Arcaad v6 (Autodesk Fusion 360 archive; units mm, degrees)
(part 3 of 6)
sketch "Sketch4" plane through (0, 7.7192, 43.7775) normal (0, 0.1736, 0.9848) x axis (1, 0, 0)
  line L1 (-288, 337.4354) -> (-288, 349.4354)
  line L2 (288, 337.4354) -> (-288, 337.4354)
  line L3 (288, 349.4354) -> (288, 337.4354)
  line L4 (-288, 349.4354) -> (288, 349.4354)
  line L5 (288, 349.4354) -> (-288, 349.4354)
  line L6 (288, 337.4354) -> (288, 349.4354)
  line L7 (-288, 337.4354) -> (288, 337.4354)
  line L8 (-288, 349.4354) -> (-288, 337.4354)
  line L9 (288, 343.4354) -> (-288, 343.4354)
  line L10 (110, -245.5646) -> (110, 244.4354)
  line L11 (-110, -245.5646) -> (110, -245.5646)
  line L12 (-110, 244.4354) -> (-110, -245.5646)
  line L13 (110, 244.4354) -> (-110, 244.4354)
  line L14 (288, 249.4354) -> (288, 149.4354)
  line L15 (294, 249.4354) -> (288, 249.4354)
  line L16 (294, 224.4354) -> (294, 249.4354)
  line L17 (300, 224.4354) -> (294, 224.4354)
  line L18 (300, 349.4354) -> (300, 224.4354)
  line L19 (150, 349.4354) -> (300, 349.4354)
  line L20 (150, 343.4354) -> (150, 349.4354)
  line L21 (175, 343.4354) -> (150, 343.4354)
  line L22 (175, 337.4354) -> (175, 343.4354)
  line L23 (75, 337.4354) -> (175, 337.4354)
  line L24 (75, 343.4354) -> (75, 337.4354)
  line L25 (100, 343.4354) -> (75, 343.4354)
  line L26 (100, 349.4354) -> (100, 343.4354)
  line L27 (-75, 349.4354) -> (100, 349.4354)
  line L28 (-75, 343.4354) -> (-75, 349.4354)
  line L29 (-50, 343.4354) -> (-75, 343.4354)
  line L30 (-50, 337.4354) -> (-50, 343.4354)
  line L31 (-175, 337.4354) -> (-50, 337.4354)
  line L32 (-175, 343.4354) -> (-175, 337.4354)
  line L33 (-150, 343.4354) -> (-175, 343.4354)
  line L34 (-150, 349.4354) -> (-150, 343.4354)
  line L35 (-300, 349.4354) -> (-150, 349.4354)
  line L36 (-300, 224.4354) -> (-300, 349.4354)
  line L37 (-294, 224.4354) -> (-300, 224.4354)
  line L38 (-294, 249.4354) -> (-294, 224.4354)
  line L39 (-288, 249.4354) -> (-294, 249.4354)
  line L40 (-288, 149.4354) -> (-288, 249.4354)
  line L41 (-294, 149.4354) -> (-288, 149.4354)
  line L42 (-294, 174.4354) -> (-294, 149.4354)
  line L43 (-300, 174.4354) -> (-294, 174.4354)
  line L44 (-300, 24.4354) -> (-300, 174.4354)
  line L45 (-294, 24.4354) -> (-300, 24.4354)
  line L46 (-294, 49.4354) -> (-294, 24.4354)
  line L47 (-288, 49.4354) -> (-294, 49.4354)
  line L48 (-288, -50.5646) -> (-288, 49.4354)
  line L49 (-294, -50.5646) -> (-288, -50.5646)
  line L50 (-294, -25.5646) -> (-294, -50.5646)
  line L51 (-300, -25.5646) -> (-294, -25.5646)
  line L52 (-300, -175.5646) -> (-300, -25.5646)
  line L53 (-294, -175.5646) -> (-300, -175.5646)
  line L54 (-294, -150.5646) -> (-294, -175.5646)
  line L55 (-288, -150.5646) -> (-294, -150.5646)
  line L56 (-288, -250.5646) -> (-288, -150.5646)
  line L57 (-294, -250.5646) -> (-288, -250.5646)
  line L58 (-294, -225.5646) -> (-294, -250.5646)
  line L59 (-300, -225.5646) -> (-294, -225.5646)
  line L60 (-300, -350.5646) -> (-300, -225.5646)
  line L61 (-150, -350.5646) -> (-300, -350.5646)
  line L62 (-150, -344.5646) -> (-150, -350.5646)
  line L63 (-175, -344.5646) -> (-150, -344.5646)
  line L64 (-175, -338.5646) -> (-175, -344.5646)
  line L65 (-75, -338.5646) -> (-175, -338.5646)
  line L66 (-75, -344.5646) -> (-75, -338.5646)
  line L67 (-100, -344.5646) -> (-75, -344.5646)
  line L68 (-100, -350.5646) -> (-100, -344.5646)
  line L69 (100, -350.5646) -> (-100, -350.5646)
  line L70 (100, -344.5646) -> (100, -350.5646)
  line L71 (75, -344.5646) -> (100, -344.5646)
  line L72 (75, -338.5646) -> (75, -344.5646)
  line L73 (175, -338.5646) -> (75, -338.5646)
  line L74 (175, -344.5646) -> (175, -338.5646)
  line L75 (150, -344.5646) -> (175, -344.5646)
  line L76 (150, -350.5646) -> (150, -344.5646)
  line L77 (300, -350.5646) -> (150, -350.5646)
  line L78 (300, -225.5646) -> (300, -350.5646)
  line L79 (294, -225.5646) -> (300, -225.5646)
  line L80 (294, -250.5646) -> (294, -225.5646)
  line L81 (288, -250.5646) -> (294, -250.5646)
  line L82 (288, -150.5646) -> (288, -250.5646)
  line L83 (294, -150.5646) -> (288, -150.5646)
  line L84 (294, -175.5646) -> (294, -150.5646)
  line L85 (300, -175.5646) -> (294, -175.5646)
  line L86 (300, -25.5646) -> (300, -175.5646)
  line L87 (294, -25.5646) -> (300, -25.5646)
  line L88 (294, -50.5646) -> (294, -25.5646)
  line L89 (288, -50.5646) -> (294, -50.5646)
  line L90 (288, 49.4354) -> (288, -50.5646)
  line L91 (294, 49.4354) -> (288, 49.4354)
  line L92 (294, 24.4354) -> (294, 49.4354)
  line L93 (300, 24.4354) -> (294, 24.4354)
  line L94 (300, 174.4354) -> (300, 24.4354)
  line L95 (294, 174.4354) -> (300, 174.4354)
  line L96 (294, 149.4354) -> (294, 174.4354)
  line L97 (288, 149.4354) -> (294, 149.4354)
  line L98 (-175, 349.4354) -> (-175, 343.4354)
  line L99 (-50, 349.4354) -> (-50, 343.4354)
  line L100 (175, 349.4354) -> (175, 343.4354)
  line L101 (75, 349.4354) -> (75, 343.4354)
  line L102 (100, 337.4354) -> (100, 343.4354)
  line L103 (150, 337.4354) -> (150, 343.4354)
  line L104 (-75, 337.4354) -> (-75, 343.4354)
  line L105 (-150, 337.4354) -> (-150, 343.4354)
  point P4 (288, 337.4354)
  point P8 (288, 337.4354)
  point P2 (-288, 349.4354)
  point P6 (-288, 349.4354)
  point P35 (-175, 343.4354)
  point P100 (-175, 343.4354)
  point P101 (-175, 349.4354)
  point P32 (-50, 343.4354)
  point P102 (-50, 343.4354)
  point P24 (175, 343.4354)
  point P104 (175, 343.4354)
  point P27 (75, 343.4354)
  point P106 (75, 343.4354)
  point P28 (100, 343.4354)
  point P108 (100, 343.4354)
  point P23 (150, 343.4354)
  point P110 (150, 343.4354)
  point P31 (-75, 343.4354)
  point P112 (-75, 343.4354)
  point P36 (-150, 343.4354)
  point P114 (-150, 343.4354)
  point P103 (-50, 349.4354)
  point P105 (175, 349.4354)
  point P107 (75, 349.4354)
  point P109 (100, 337.4354)
  point P111 (150, 337.4354)
  point P113 (-75, 337.4354)
  point P115 (-150, 337.4354)
  horizontal L5
  vertical L6
  horizontal L7
  vertical L8
  coincident P4 P8
  coincident P2 P6
  coincident P35 P100
  coincident L5 P101
  coincident P32 P102
  perpendicular L5 L99
  coincident P24 P104
  perpendicular L5 L100
  coincident P27 P106
  perpendicular L27 L101
  coincident P28 P108
  perpendicular L7 L102
  coincident P23 P110
  perpendicular L23 L103
  coincident P31 P112
  perpendicular L7 L104
  coincident P36 P114
  perpendicular L31 L105
  dimension "d37" = 6
  dimension "d201" distance P100 P101 = 6
  dimension "d202" distance P102 P103 = 6
  dimension "d203" distance P104 P105 = 6
  dimension "d204" distance P106 P107 = 6
  dimension "d205" distance P108 P109 = 6
  dimension "d206" distance P110 P111 = 6
  dimension "d207" distance P112 P113 = 6
  dimension "d208" distance P114 P115 = 6
extrude "Extrude5" add sketch "Sketch4" profile of L2 L4 L5 L7 L9 L19 L20 L21 L23 L25 L26 L27 L28 L29 L31 L33 L34 L35 L98 L99 L100 L101 L102 L103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 along normal blind 12
sketch "Sketch5" plane through (0, 7.7192, 43.7775) normal (0, 0.1736, 0.9848) x axis (1, 0, 0)
  line L1 (175, 349.4354) -> (288, 349.4354)
  line L2 (288, 337.4354) -> (150, 337.4354)
  line L3 (110, -245.5646) -> (110, 244.4354)
  line L4 (-110, -245.5646) -> (110, -245.5646)
  line L5 (-110, 244.4354) -> (-110, -245.5646)
  line L6 (110, 244.4354) -> (-110, 244.4354)
  line L7 (288, 249.4354) -> (288, 149.4354)
  line L8 (294, 249.4354) -> (288, 249.4354)
  line L9 (294, 224.4354) -> (294, 249.4354)
  line L10 (300, 224.4354) -> (294, 224.4354)
  line L11 (300, 349.4354) -> (300, 224.4354)
  line L12 (150, 349.4354) -> (300, 349.4354)
  line L13 (150, 343.4354) -> (150, 349.4354)
  line L14 (175, 343.4354) -> (150, 343.4354)
  line L15 (175, 337.4354) -> (175, 343.4354)
  line L16 (75, 337.4354) -> (175, 337.4354)
  line L17 (75, 343.4354) -> (75, 337.4354)
  line L18 (100, 343.4354) -> (75, 343.4354)
  line L19 (100, 349.4354) -> (100, 343.4354)
  line L20 (-75, 349.4354) -> (100, 349.4354)
  line L21 (-75, 343.4354) -> (-75, 349.4354)
  line L22 (-50, 343.4354) -> (-75, 343.4354)
  line L23 (-50, 337.4354) -> (-50, 343.4354)
  line L24 (-175, 337.4354) -> (-50, 337.4354)
  line L25 (-175, 343.4354) -> (-175, 337.4354)
  line L26 (-150, 343.4354) -> (-175, 343.4354)
  line L27 (-150, 349.4354) -> (-150, 343.4354)
  line L28 (-300, 349.4354) -> (-150, 349.4354)
  line L29 (-300, 224.4354) -> (-300, 349.4354)
  line L30 (-294, 224.4354) -> (-300, 224.4354)
  line L31 (-294, 249.4354) -> (-294, 224.4354)
  line L32 (-288, 249.4354) -> (-294, 249.4354)
  line L33 (-288, 149.4354) -> (-288, 249.4354)
  line L34 (-294, 149.4354) -> (-288, 149.4354)
  line L35 (-294, 174.4354) -> (-294, 149.4354)
  line L36 (-300, 174.4354) -> (-294, 174.4354)
  line L37 (-300, 24.4354) -> (-300, 174.4354)
  line L38 (-294, 24.4354) -> (-300, 24.4354)
  line L39 (-294, 49.4354) -> (-294, 24.4354)
  line L40 (-288, 49.4354) -> (-294, 49.4354)
  line L41 (-288, -50.5646) -> (-288, 49.4354)
  line L42 (-294, -50.5646) -> (-288, -50.5646)
  line L43 (-294, -25.5646) -> (-294, -50.5646)
  line L44 (-300, -25.5646) -> (-294, -25.5646)
  line L45 (-300, -175.5646) -> (-300, -25.5646)
  line L46 (-294, -175.5646) -> (-300, -175.5646)
  line L47 (-294, -150.5646) -> (-294, -175.5646)
  line L48 (-288, -150.5646) -> (-294, -150.5646)
  line L49 (-288, -250.5646) -> (-288, -150.5646)
  line L50 (-294, -250.5646) -> (-288, -250.5646)
  line L51 (-294, -225.5646) -> (-294, -250.5646)
  line L52 (-300, -225.5646) -> (-294, -225.5646)
  line L53 (-300, -350.5646) -> (-300, -225.5646)
  line L54 (-150, -350.5646) -> (-300, -350.5646)
  line L55 (-150, -344.5646) -> (-150, -350.5646)
  line L56 (-175, -344.5646) -> (-150, -344.5646)
  line L57 (-175, -338.5646) -> (-175, -344.5646)
  line L58 (-75, -338.5646) -> (-175, -338.5646)
  line L59 (-75, -344.5646) -> (-75, -338.5646)
  line L60 (-100, -344.5646) -> (-75, -344.5646)
  line L61 (-100, -350.5646) -> (-100, -344.5646)
  line L62 (100, -350.5646) -> (-100, -350.5646)
  line L63 (100, -344.5646) -> (100, -350.5646)
  line L64 (75, -344.5646) -> (100, -344.5646)
  line L65 (75, -338.5646) -> (75, -344.5646)
  line L66 (175, -338.5646) -> (75, -338.5646)
  line L67 (175, -344.5646) -> (175, -338.5646)
  line L68 (150, -344.5646) -> (175, -344.5646)
  line L69 (150, -350.5646) -> (150, -344.5646)
  line L70 (300, -350.5646) -> (150, -350.5646)
  line L71 (300, -225.5646) -> (300, -350.5646)
  line L72 (294, -225.5646) -> (300, -225.5646)
  line L73 (294, -250.5646) -> (294, -225.5646)
  line L74 (288, -250.5646) -> (294, -250.5646)
  line L75 (288, -150.5646) -> (288, -250.5646)
  line L76 (294, -150.5646) -> (288, -150.5646)
  line L77 (294, -175.5646) -> (294, -150.5646)
  line L78 (300, -175.5646) -> (294, -175.5646)
  line L79 (300, -25.5646) -> (300, -175.5646)
  line L80 (294, -25.5646) -> (300, -25.5646)
  line L81 (294, -50.5646) -> (294, -25.5646)
  line L82 (288, -50.5646) -> (294, -50.5646)
  line L83 (288, 49.4354) -> (288, -50.5646)
  line L84 (294, 49.4354) -> (288, 49.4354)
  line L85 (294, 24.4354) -> (294, 49.4354)
  line L86 (300, 24.4354) -> (294, 24.4354)
  line L87 (300, 174.4354) -> (300, 24.4354)
  line L88 (294, 174.4354) -> (300, 174.4354)
  line L89 (294, 149.4354) -> (294, 174.4354)
  line L90 (288, 149.4354) -> (294, 149.4354)
  line L91 (288, 337.4354) -> (-288, 337.4354)
  line L92 (288, 387.4354) -> (288, 337.4354)
  line L93 (-288, 387.4354) -> (288, 387.4354)
  line L94 (-288, 337.4354) -> (-288, 387.4354)
  line L95 (288, 349.4354) -> (-288, 349.4354)
  line L96 (288, 337.4354) -> (288, 349.4354)
  line L97 (-288, 337.4354) -> (288, 337.4354)
  line L98 (-288, 349.4354) -> (-288, 337.4354)
  line L99 (-288, 349.4354) -> (288, 349.4354)
  line L100 (-288, 337.4354) -> (-288, 349.4354)
  line L101 (288, 337.4354) -> (-288, 337.4354)
  line L102 (288, 349.4354) -> (288, 337.4354)
  line L103 (150, 337.4354) -> (150, 343.4354)
  line L104 (288, 349.4354) -> (288, 337.4354)
  line L105 (175, 343.4354) -> (175, 349.4354)
  line L106 (150, 343.4354) -> (175, 343.4354)
  line L107 (-150, 343.4354) -> (-150, 337.4354)
  line L108 (-175, 343.4354) -> (-150, 343.4354)
  line L109 (-175, 349.4354) -> (-175, 343.4354)
  line L110 (-288, 349.4354) -> (-175, 349.4354)
  line L111 (-288, 337.4354) -> (-288, 349.4354)
  line L112 (-150, 337.4354) -> (-288, 337.4354)
  line L113 (-50, 349.4354) -> (-50, 337.4354)
  line L114 (-75, 337.4354) -> (-75, 343.4354)
  line L115 (150, 337.4354) -> (150, 343.4354)
  line L116 (100, 337.4354) -> (100, 343.4354)
  line L117 (75, 349.4354) -> (75, 343.4354)
  line L118 (175, 349.4354) -> (175, 343.4354)
  line L119 (-150, 349.4354) -> (-150, 343.4354)
  line L120 (-75, 349.4354) -> (-75, 343.4354)
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  point P94 (-288, 337.4354)
  point P98 (-288, 337.4354)
  point P99 (-288, 349.4354)
  point P102 (-288, 349.4354)
  point P104 (-288, 337.4354)
  point P27 (-50, 337.4354)
  point P115 (-50, 337.4354)
  point P114 (-50, 349.4354)
  point P116 (-50, 349.4354)
  point P25 (-75, 343.4354)
  point P118 (-75, 343.4354)
  point P117 (-75, 337.4354)
  point P119 (-75, 337.4354)
  point P106 (150, 343.4354)
  point P120 (150, 343.4354)
  point P5 (150, 337.4354)
  point P121 (150, 337.4354)
  point P22 (100, 343.4354)
  point P123 (100, 343.4354)
  point P122 (100, 337.4354)
  point P124 (100, 337.4354)
  point P21 (75, 343.4354)
  point P126 (75, 343.4354)
  point P125 (75, 349.4354)
  point P127 (75, 349.4354)
  point P107 (175, 343.4354)
  point P128 (175, 343.4354)
  point P4 (175, 349.4354)
  point P129 (175, 349.4354)
  point P109 (-150, 343.4354)
  point P130 (-150, 343.4354)
  point P31 (-150, 349.4354)
  point P131 (-150, 349.4354)
  point P132 (-75, 343.4354)
  point P24 (-75, 349.4354)
  point P133 (-75, 349.4354)
  point P134 (100, 343.4354)
  point P23 (100, 349.4354)
  point P135 (100, 349.4354)
  point P17 (150, 343.4354)
  point P136 (150, 343.4354)
  point P16 (150, 349.4354)
  point P137 (150, 349.4354)
  point P97 (-288, 387.4354)
  horizontal L91
  vertical L92
  horizontal L93
  vertical L94
  coincident P94 P98
  horizontal L95
  vertical L96
  horizontal L97
  vertical L98
  coincident P99 P102
  horizontal L99
  vertical L100
  horizontal L101
  vertical L102
  coincident P98 P104
  coincident P27 P115
  coincident P114 P116
  coincident P25 P118
  coincident P117 P119
  coincident P106 P120
  coincident P5 P121
  coincident P22 P123
  coincident P122 P124
  coincident P21 P126
  coincident P125 P127
  coincident P107 P128
  coincident P4 P129
  coincident P109 P130
  coincident P31 P131
  coincident P25 P132
  coincident P24 P133
  coincident P22 P134
  coincident P23 P135
  coincident P17 P136
  coincident P16 P137
  dimension "d40" distance P94 P97 = 50
extrude "Extrude6" new body sketch "Sketch5" to an object
sketch "Sketch6" plane through (-288, 0, 0) normal (-1, 0, 0) x axis (0, 0, 1)
  line L1 (-64.0579, 331.3458) -> (-66.1417, 343.1635)
  line L2 (-14.8175, 340.0282) -> (-64.0579, 331.3458)
  line L3 (-16.9013, 351.8459) -> (-14.8175, 340.0282)
  line L4 (-66.1417, 343.1635) -> (-16.9013, 351.8459)
  line L5 (-11.6822, 391.3524) -> (-2.9998, 342.112)
  line L6 (-23.4999, 389.2686) -> (-11.6822, 391.3524)
  line L7 (-14.8175, 340.0282) -> (-23.4999, 389.2686)
  line L8 (-66.1417, 343.1635) -> (55.412, -346.2019)
  line L9 (-312.3436, 299.7514) -> (-66.1417, 343.1635)
  line L10 (-190.7899, -389.614) -> (-312.3436, 299.7514)
  line L11 (55.412, -346.2019) -> (-190.7899, -389.614)
  line L12 (-344.588, -346.2019) -> (55.412, -346.2019)
  line L13 (-312.3436, -346.2019) -> (-312.3436, 299.7514)
  line L14 (-312.3436, 426.9121) -> (-312.3436, -346.2019)
  line L15 (-312.3436, 389.2686) -> (-23.4999, 389.2686)
  line L16 (-64.0579, 331.3458) -> (-14.8175, 340.0282)
  line L17 (-2.9998, 342.112) -> (-14.8175, 340.0282)
  point P10 (55.412, -346.2019)
  point P14 (55.412, -346.2019)
  point P12 (-312.3436, 299.7514)
  point P16 (-312.3436, 299.7514)
  point P17 (-312.3436, -346.2019)
  point P8 (-23.4999, 389.2686)
  point P19 (-23.4999, 389.2686)
  point P20 (-312.3436, 389.2686)
  point P9 (-14.8175, 340.0282)
  point P21 (-14.8175, 340.0282)
  point P3 (-64.0579, 331.3458)
  point P22 (-64.0579, 331.3458)
  point P15 (-344.588, -346.2019)
  coincident P10 P14
  coincident P12 P16
  coincident L12 P17
  perpendicular L12 L13
  parallel L13 L14
  coincident P8 P19
  coincident L14 P20
  perpendicular L14 L15
  coincident P9 P21
  coincident P3 P22
  dimension "d43" distance P14 P15 = 400
  dimension "d44" angle L8 L12 = 80
extrude "Extrude7" add sketch "Sketch6" profile of L1 L2 L3 L4 L5 L6 L7 L8 L9 L10 L12 L13 L14 L15 L16 to an object
sketch "Sketch7" plane through (288, 0, 0) normal (1, 0, 0) x axis (0, 0, -1)
  line L1 (66.1417, 343.1635) -> (64.0579, 331.3458)
  line L2 (16.9013, 351.8459) -> (66.1417, 343.1635)
  line L3 (14.8175, 340.0282) -> (16.9013, 351.8459)
  line L4 (64.0579, 331.3458) -> (14.8175, 340.0282)
  line L5 (-55.412, -346.2019) -> (64.0579, 331.3458)
  line L6 (190.7899, -389.614) -> (-55.412, -346.2019)
  line L7 (198.4446, -346.2019) -> (190.7899, -389.614)
  line L8 (312.3436, -346.2019) -> (198.4446, -346.2019)
  line L9 (312.3436, 389.2686) -> (312.3436, -346.2019)
  line L10 (23.4999, 389.2686) -> (312.3436, 389.2686)
  line L11 (11.6822, 391.3524) -> (23.4999, 389.2686)
  line L12 (2.9998, 342.112) -> (11.6822, 391.3524)
  line L13 (64.0579, 331.3458) -> (2.9998, 342.112)
extrude "Extrude8" add sketch "Sketch7" along normal blind 12
combine "Combine1"
combine "Combine2"
sketch "Sketch8" plane through (300, 0, 0) normal (1, 0, 0) x axis (0, 0, -1)
  line L1 (-21.8883, -225.1847) -> (-43.5944, -348.2857)
  line L2 (-33.706, -223.101) -> (-21.8883, -225.1847)
  line L3 (-55.412, -346.2019) -> (-33.706, -223.101)
  line L4 (-43.5944, -348.2857) -> (-55.412, -346.2019)
  line L5 (-287.6564, -346.2019) -> (312.3436, -346.2019)
  line L6 (-287.6564, -596.2019) -> (-287.6564, -346.2019)
  line L7 (312.3436, -596.2019) -> (-287.6564, -596.2019)
  line L8 (312.3436, -346.2019) -> (312.3436, -596.2019)
  line L9 (312.3436, -471.2019) -> (-287.6564, -471.2019)
  line L10 (-287.6564, -408.7019) -> (312.3436, -408.7019)
  line L11 (-287.6564, -408.7019) -> (-55.412, -346.2019)
  point P6 (312.3436, -346.2019)
  point P10 (312.3436, -346.2019)
  point P5 (-55.412, -346.2019)
  point P15 (-55.412, -346.2019)
  point P9 (312.3436, -596.2019)
  point P7 (-287.6564, -346.2019)
  horizontal L5
  vertical L6
  horizontal L7
  vertical L8
  coincident P6 P10
  coincident P5 P15
  dimension "d49" distance P6 P9 = 250
  dimension "d50" distance P6 P7 = 600
  dimension "d51" = -125 (= "-( ( 250 / 2 ) * 1 mm )")
  dimension "d52" = -62.5 (= "-( ( 250 / 4 ) * 1 mm )")
extrude "Extrude9" add sketch "Sketch8" profile of L1 L4 L5 L6 L7 L8 L9 L10 L11 against normal blind 12
sketch "Sketch9" plane through (-300, 0, 0) normal (-1, 0, 0) x axis (0, 0, 1)
  line L1 (13.2059, -175.9444) -> (25.0236, -173.8606)
  line L2 (-12.8413, -28.2232) -> (13.2059, -175.9444)
  line L3 (-1.0236, -26.1394) -> (-12.8413, -28.2232)
  line L4 (-9.706, 23.101) -> (-1.0236, -26.1394)
  line L5 (-21.5237, 21.0172) -> (-9.706, 23.101)
  line L6 (-47.5709, 168.7384) -> (-21.5237, 21.0172)
  line L7 (-35.7532, 170.8221) -> (-47.5709, 168.7384)
  line L8 (-44.4357, 220.0625) -> (-35.7532, 170.8221)
  line L9 (-56.2534, 217.9787) -> (-44.4357, 220.0625)
  line L10 (-77.9594, 341.0797) -> (-56.2534, 217.9787)
  line L11 (-66.1417, 343.1635) -> (-77.9594, 341.0797)
  line L12 (-64.0579, 331.3458) -> (-66.1417, 343.1635)
  line L13 (-2.9998, 342.112) -> (-64.0579, 331.3458)
  line L14 (-11.6822, 391.3524) -> (-2.9998, 342.112)
  line L15 (-23.4999, 389.2686) -> (-11.6822, 391.3524)
  line L16 (-312.3436, 389.2686) -> (-23.4999, 389.2686)
  line L17 (-312.3436, -346.2019) -> (-312.3436, 389.2686)
  line L18 (-198.4446, -346.2019) -> (-312.3436, -346.2019)
  line L19 (-190.7899, -389.614) -> (-198.4446, -346.2019)
  line L20 (43.5944, -348.2857) -> (-190.7899, -389.614)
  line L21 (21.8883, -225.1847) -> (43.5944, -348.2857)
  line L22 (33.706, -223.101) -> (21.8883, -225.1847)
  line L23 (25.0236, -173.8606) -> (33.706, -223.101)
  line L24 (26.2295, -249.8049) -> (43.5944, -348.2857)
  line L25 (38.0472, -247.7212) -> (26.2295, -249.8049)
  line L26 (20.6824, -149.2404) -> (38.0472, -247.7212)
  line L27 (8.8647, -151.3242) -> (20.6824, -149.2404)
  line L28 (-8.5001, -52.8434) -> (8.8647, -151.3242)
  line L29 (3.3176, -50.7596) -> (-8.5001, -52.8434)
  line L30 (-14.0472, 47.7212) -> (3.3176, -50.7596)
  line L31 (-25.8649, 45.6374) -> (-14.0472, 47.7212)
  line L32 (-43.2297, 144.1182) -> (-25.8649, 45.6374)
  line L33 (-31.412, 146.2019) -> (-43.2297, 144.1182)
  line L34 (-48.7769, 244.6827) -> (-31.412, 146.2019)
  line L35 (-60.5946, 242.5989) -> (-48.7769, 244.6827)
  line L36 (-77.9594, 341.0797) -> (-60.5946, 242.5989)
  line L37 (-66.1417, 343.1635) -> (-77.9594, 341.0797)
  line L38 (-64.0579, 331.3458) -> (-66.1417, 343.1635)
  line L39 (-2.9998, 342.112) -> (-64.0579, 331.3458)
  line L40 (-11.6822, 391.3524) -> (-2.9998, 342.112)
  line L41 (-23.4999, 389.2686) -> (-11.6822, 391.3524)
  line L42 (-312.3436, 389.2686) -> (-23.4999, 389.2686)
  line L43 (-312.3436, -596.2019) -> (-312.3436, 389.2686)
  line L44 (287.6564, -596.2019) -> (-312.3436, -596.2019)
  line L45 (287.6564, -408.7019) -> (287.6564, -596.2019)
  line L46 (55.412, -346.2019) -> (287.6564, -408.7019)
  line L47 (43.5944, -348.2857) -> (55.412, -346.2019)
  line L48 (43.5944, -348.2857) -> (21.8883, -225.1847)
  line L49 (55.412, -346.2019) -> (43.5944, -348.2857)
  line L50 (33.706, -223.101) -> (55.412, -346.2019)
  line L51 (21.8883, -225.1847) -> (33.706, -223.101)
  line L52 (13.2059, -175.9444) -> (-12.8413, -28.2232)
  line L53 (25.0236, -173.8606) -> (13.2059, -175.9444)
  line L54 (-1.0236, -26.1394) -> (25.0236, -173.8606)
  line L55 (-12.8413, -28.2232) -> (-1.0236, -26.1394)
  line L56 (-21.5237, 21.0172) -> (-47.5709, 168.7384)
  line L57 (-9.706, 23.101) -> (-21.5237, 21.0172)
  line L58 (-35.7532, 170.8221) -> (-9.706, 23.101)
  line L59 (-47.5709, 168.7384) -> (-35.7532, 170.8221)
  line L60 (-56.2534, 217.9787) -> (-77.9594, 341.0797)
  line L61 (-44.4357, 220.0625) -> (-56.2534, 217.9787)
  line L62 (-66.1417, 343.1635) -> (-44.4357, 220.0625)
  line L63 (-77.9594, 341.0797) -> (-66.1417, 343.1635)
extrude "Extrude10" add sketch "Sketch9" profile of L18 L19 L20 L43 L44 L45 L46 L47 L49 against normal blind 12
extrude "Extrude11" add of existing geometry to an object
sketch "Sketch10" plane through (0, 0, 287.6564) normal (0, 0, 1) x axis (1, 0, 0)
  line L1 (-300, -596.2019) -> (-300, -408.7019)
  line L2 (-288, -596.2019) -> (-300, -596.2019)
  line L3 (-288, -408.7019) -> (-288, -596.2019)
  line L4 (-300, -408.7019) -> (-288, -408.7019)
  line L5 (300, -408.7019) -> (-300, -408.7019)
  line L6 (300, -596.2019) -> (300, -408.7019)
  line L7 (-300, -596.2019) -> (300, -596.2019)
  line L8 (-300, -408.7019) -> (-300, -596.2019)
  line L9 (300, -408.7019) -> (300, -596.2019)
  line L10 (288, -408.7019) -> (300, -408.7019)
  line L11 (288, -596.2019) -> (288, -408.7019)
  line L12 (300, -596.2019) -> (288, -596.2019)
  line L13 (300, -502.4519) -> (-300, -502.4519)
  line L14 (300, -552.4519) -> (-300, -552.4519)
  line L15 (300, -527.4519) -> (-300, -527.4519)
  line L16 (300, -477.4519) -> (-300, -477.4519)
  line L17 (300, -452.4519) -> (-300, -452.4519)
  line L18 (-294, -408.7019) -> (-294, -596.2019)
  line L19 (294, -596.2019) -> (294, -408.7019)
  point P8 (300, -596.2019)
  point P10 (300, -596.2019)
  point P2 (-300, -408.7019)
  point P6 (-300, -408.7019)
  point P15 (-300, -502.4519)
  point P16 (300, -502.4519)
  horizontal L5
  vertical L6
  horizontal L7
  vertical L8
  coincident P8 P10
  coincident P2 P6
  midpoint L8 P15
  midpoint L9 P16
  dimension "d59" = 50
  dimension "d60" = 25 (= "( 50 / 2 ) * 1 mm")
  dimension "d61" = -25 (= "-( ( 50 / 2 ) * 1 mm )")
  dimension "d62" = -50
  dimension "d63" = 6
  dimension "d64" = 6
extrude "Extrude12" add sketch "Sketch10" profile of L1 L3 L6 L8 L9 L11 L13 L14 L15 L16 L17 L18 L19 along normal blind 12
extrude "Extrude13" new body sketch "Sketch10" along normal blind 12
sketch "Sketch11" plane through (-300, 0, 0) normal (-1, 0, 0) x axis (0, 0, 1)
  line L1 (13.2059, -175.9444) -> (25.0236, -173.8606)
  line L2 (-12.8413, -28.2232) -> (13.2059, -175.9444)
  line L3 (-1.0236, -26.1394) -> (-12.8413, -28.2232)
  line L4 (-9.706, 23.101) -> (-1.0236, -26.1394)
  line L5 (-21.5237, 21.0172) -> (-9.706, 23.101)
  line L6 (-47.5709, 168.7384) -> (-21.5237, 21.0172)
  line L7 (-35.7532, 170.8221) -> (-47.5709, 168.7384)
  line L8 (-44.4357, 220.0625) -> (-35.7532, 170.8221)
  line L9 (-56.2534, 217.9787) -> (-44.4357, 220.0625)
  line L10 (-77.9594, 341.0797) -> (-56.2534, 217.9787)
  line L11 (-66.1417, 343.1635) -> (-77.9594, 341.0797)
  line L12 (-64.0579, 331.3458) -> (-66.1417, 343.1635)
  line L13 (-2.9998, 342.112) -> (-64.0579, 331.3458)
  line L14 (-11.6822, 391.3524) -> (-2.9998, 342.112)
  line L15 (-23.4999, 389.2686) -> (-11.6822, 391.3524)
  line L16 (-312.3436, 389.2686) -> (-23.4999, 389.2686)
  line L17 (-312.3436, -596.2019) -> (-312.3436, 389.2686)
  line L18 (287.6564, -596.2019) -> (-312.3436, -596.2019)
  line L19 (287.6564, -527.4519) -> (287.6564, -596.2019)
  line L20 (299.6564, -527.4519) -> (287.6564, -527.4519)
  line L21 (299.6564, -477.4519) -> (299.6564, -527.4519)
  line L22 (287.6564, -477.4519) -> (299.6564, -477.4519)
  line L23 (287.6564, -408.7019) -> (287.6564, -477.4519)
  line L24 (55.412, -346.2019) -> (287.6564, -408.7019)
  line L25 (43.5944, -348.2857) -> (55.412, -346.2019)
  line L26 (21.8883, -225.1847) -> (43.5944, -348.2857)
  line L27 (33.706, -223.101) -> (21.8883, -225.1847)
  line L28 (25.0236, -173.8606) -> (33.706, -223.101)
  line L29 (52.2936, -357.7897) -> (284.538, -420.2897)
  line L30 (168.4158, -389.0397) -> (171.5342, -377.4519)
  line L31 (139.4465, -381.2436) -> (142.5649, -369.6559)
  line L32 (197.3851, -396.8357) -> (200.5035, -385.248)
  line L33 (207.0416, -399.4344) -> (210.16, -387.8466)
  line L34 (129.79, -378.645) -> (132.9084, -367.0572)
  line L35 (53.8528, -351.9958) -> (286.0972, -414.4958)
  point P32 (171.5342, -377.4519)
  point P33 (168.4158, -389.0397)
  midpoint L24 P32
  midpoint L29 P33
  perpendicular L29 L30
  dimension "d69" = -12
  dimension "d70" = 30
  dimension "d71" = -30
  dimension "d72" = -40
  dimension "d73" = 40
  dimension "d74" = -6
extrude "Extrude14" cut sketch "Sketch11" profile of L24 L29 L30 L31 L32 L33 L34 L35 to an object
sketch "Sketch12" plane through (0, -308.9174, -83.1337) normal (0, 0.9656, 0.2599) x axis (1, 0, 0)
  line L1 (-288, -233.7285) -> (-300, -233.7285)
  line L2 (-288, -143.475) -> (-288, -233.7285)
  line L3 (-300, -143.475) -> (-288, -143.475)
  line L4 (-300, -233.7285) -> (-300, -143.475)
  line L5 (-288, -223.7285) -> (-288, -303.7285)
  line L6 (-300, -223.7285) -> (-288, -223.7285)
  line L7 (-300, -303.7285) -> (-300, -223.7285)
  line L8 (-288, -303.7285) -> (-300, -303.7285)
  line L9 (-300, -293.7285) -> (-288, -293.7285)
  line L10 (-300, -383.9821) -> (-300, -293.7285)
  line L11 (-288, -383.9821) -> (-300, -383.9821)
  line L12 (-288, -293.7285) -> (-288, -383.9821)
  line L13 (300, -233.7285) -> (288, -233.7285)
  line L14 (300, -143.475) -> (300, -233.7285)
  line L15 (288, -143.475) -> (300, -143.475)
  line L16 (288, -233.7285) -> (288, -143.475)
  line L17 (288, -303.7285) -> (288, -223.7285)
  line L18 (300, -303.7285) -> (288, -303.7285)
  line L19 (300, -223.7285) -> (300, -303.7285)
  line L20 (288, -223.7285) -> (300, -223.7285)
  line L21 (288, -293.7285) -> (300, -293.7285)
  line L22 (288, -383.9821) -> (288, -293.7285)
  line L23 (300, -383.9821) -> (288, -383.9821)
  line L24 (300, -293.7285) -> (300, -383.9821)
  line L25 (288, -143.475) -> (-288, -143.475)
  line L26 (288, -383.9821) -> (288, -143.475)
  line L27 (-288, -383.9821) -> (288, -383.9821)
  line L28 (-288, -143.475) -> (-288, -383.9821)
  point P24 (288, -383.9821)
  point P28 (288, -383.9821)
  point P4 (-288, -143.475)
  point P26 (-288, -143.475)
  horizontal L25
  vertical L26
  horizontal L27
  vertical L28
  coincident P24 P28
  coincident P4 P26
extrude "Extrude15" new body sketch "Sketch12" against normal blind 12
combine "Combine3"
combine "Combine4"
sketch "Sketch13" plane through (0, -596.2019, 0) normal (0, -1, 0) x axis (1, 0, 0)
  line L1 (300, 287.6564) -> (300, -312.3436)
  line L2 (288, 287.6564) -> (300, 287.6564)
  line L3 (288, -312.3436) -> (288, 287.6564)
  line L4 (300, -312.3436) -> (288, -312.3436)
  line L5 (-300, -312.3436) -> (300, -312.3436)
  line L6 (-300, 299.6564) -> (-300, -312.3436)
  line L7 (300, 299.6564) -> (-300, 299.6564)
  line L8 (300, -312.3436) -> (300, 299.6564)
  line L9 (288, -300.3436) -> (288, 287.6564)
  line L10 (-288, -300.3436) -> (288, -300.3436)
  line L11 (-288, 287.6564) -> (-288, -300.3436)
  line L12 (288, 287.6564) -> (-288, 287.6564)
  line L13 (-300, -6.3436) -> (300, -6.3436)
  line L14 (0, -312.3436) -> (0, 299.6564)
  line L15 (-300, 18.6564) -> (300, 18.6564)
  line L16 (-300, -31.3436) -> (300, -31.3436)
  line L17 (-300, 33.6564) -> (300, 33.6564)
  line L18 (-300, -46.3436) -> (300, -46.3436)
  line L19 (-300, 128.6564) -> (300, 128.6564)
  line L20 (-300, 143.6564) -> (300, 143.6564)
  line L21 (-300, 193.6564) -> (300, 193.6564)
  line L22 (-300, 208.6564) -> (300, 208.6564)
  line L23 (-300, -221.3436) -> (300, -221.3436)
  line L24 (-300, -206.3436) -> (300, -206.3436)
  line L25 (-300, -156.3436) -> (300, -156.3436)
  line L26 (-300, -141.3436) -> (300, -141.3436)
  line L27 (294, -306.3436) -> (294, 293.6564)
  line L28 (-294, -306.3436) -> (294, -306.3436)
  line L29 (-294, 293.6564) -> (-294, -306.3436)
  line L30 (294, 293.6564) -> (-294, 293.6564)
  line L31 (-40, -312.3436) -> (-40, 299.6564)
  line L32 (40, -312.3436) -> (40, 299.6564)
  line L33 (-25, -312.3436) -> (-25, 299.6564)
  line L34 (25, -312.3436) -> (25, 299.6564)
  line L35 (140, -312.3436) -> (140, 299.6564)
  line L36 (155, -312.3436) -> (155, 299.6564)
  line L37 (205, -312.3436) -> (205, 299.6564)
  line L38 (220, -312.3436) -> (220, 299.6564)
  line L39 (-220, -312.3436) -> (-220, 299.6564)
  line L40 (-205, -312.3436) -> (-205, 299.6564)
  line L41 (-155, -312.3436) -> (-155, 299.6564)
  line L42 (-140, -312.3436) -> (-140, 299.6564)
  point P8 (-300, 299.6564)
  point P10 (-300, 299.6564)
  point P2 (300, -312.3436)
  point P6 (300, -312.3436)
  point P15 (300, -6.3436)
  point P16 (-300, -6.3436)
  point P17 (0, 299.6564)
  point P18 (0, -312.3436)
  horizontal L5
  vertical L6
  horizontal L7
  vertical L8
  coincident P8 P10
  coincident P2 P6
  midpoint L8 P15
  midpoint L6 P16
  midpoint L7 P17
  midpoint L5 P18
  dimension "d79" = 12
  dimension "d80" = 25
  dimension "d81" = -25
  dimension "d82" = 40
  dimension "d83" = -40
  dimension "d88" = 6
  dimension "d89" = 40
  dimension "d90" = -40
  dimension "d91" = 25
  dimension "d92" = -25
  dimension "d86" R-Pattern1-uDistance = 0
  dimension "d87" R-Pattern1-vDistance = -175
  dimension "d95" R-Pattern2-uDistance = -180
  dimension "d96" R-Pattern2-vDistance = 0
extrude "Extrude16" new body sketch "Sketch13" against normal blind 12
sketch "Sketch14" plane through (0, 389.2686, 0) normal (0, 1, 0) x axis (-1, 0, 0)
  line L1 (300, -23.4999) -> (300, -312.3436)
  line L2 (288, -23.4999) -> (300, -23.4999)
  line L3 (288, -312.3436) -> (288, -23.4999)
  line L4 (300, -312.3436) -> (288, -312.3436)
  line L5 (-300, -312.3436) -> (-300, 299.6564)
  line L6 (-205, -312.3436) -> (-300, -312.3436)
  line L7 (-205, -306.3436) -> (-205, -312.3436)
  line L8 (-220, -306.3436) -> (-205, -306.3436)
  line L9 (-220, -300.3436) -> (-220, -306.3436)
  line L10 (-140, -300.3436) -> (-220, -300.3436)
  line L11 (-140, -306.3436) -> (-140, -300.3436)
  line L12 (-155, -306.3436) -> (-140, -306.3436)
  line L13 (-155, -312.3436) -> (-155, -306.3436)
  line L14 (-25, -312.3436) -> (-155, -312.3436)
  line L15 (-25, -306.3436) -> (-25, -312.3436)
  line L16 (-40, -306.3436) -> (-25, -306.3436)
  line L17 (-40, -300.3436) -> (-40, -306.3436)
  line L18 (40, -300.3436) -> (-40, -300.3436)
  line L19 (40, -306.3436) -> (40, -300.3436)
  line L20 (25, -306.3436) -> (40, -306.3436)
  line L21 (25, -312.3436) -> (25, -306.3436)
  line L22 (155, -312.3436) -> (25, -312.3436)
  line L23 (155, -306.3436) -> (155, -312.3436)
  line L24 (140, -306.3436) -> (155, -306.3436)
  line L25 (140, -300.3436) -> (140, -306.3436)
  line L26 (220, -300.3436) -> (140, -300.3436)
  line L27 (220, -306.3436) -> (220, -300.3436)
  line L28 (205, -306.3436) -> (220, -306.3436)
  line L29 (205, -312.3436) -> (205, -306.3436)
  line L30 (300, -312.3436) -> (205, -312.3436)
  line L31 (300, 299.6564) -> (300, -312.3436)
  line L32 (-300, 299.6564) -> (300, 299.6564)
  line L33 (288, -312.3436) -> (288, -23.4999)
  line L34 (-288, -23.4999) -> (-288, -312.3436)
  line L35 (-300, -312.3436) -> (300, -312.3436)
  line L36 (-300, -23.4999) -> (-300, -312.3436)
  line L37 (300, -23.4999) -> (-300, -23.4999)
  line L38 (300, -312.3436) -> (300, -23.4999)
  line L39 (-300, -167.9218) -> (300, -167.9218)
  line L40 (294, -312.3436) -> (294, -23.4999)
  line L41 (-294, -23.4999) -> (-294, -312.3436)
  line L42 (-300, -142.9218) -> (300, -142.9218)
  line L43 (-300, -127.9218) -> (300, -127.9218)
  line L44 (-300, -192.9218) -> (300, -192.9218)
  line L45 (-300, -207.9218) -> (300, -207.9218)
  point P40 (-300, -23.4999)
  point P42 (-300, -23.4999)
  point P32 (300, -312.3436)
  point P38 (300, -312.3436)
  point P43 (300, -167.9218)
  point P44 (-300, -167.9218)
  horizontal L35
  vertical L36
  horizontal L37
  vertical L38
  coincident P40 P42
  coincident P32 P38
  midpoint L38 P43
  midpoint L36 P44
  dimension "d99" = 6
  dimension "d100" = 6
  dimension "d101" = 25
  dimension "d102" = 40
  dimension "d103" = -25
  dimension "d104" = -40
extrude "Extrude17" new body sketch "Sketch14" profile of L1 L2 L3 L4 L5 L6 L7 L8 L9 L10 L11 L12 L13 L14 L15 L16 L17 L18 L19 L20 L21 L22 L23 L24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 against normal blind 12
sketch "Sketch15" plane through (0, 0, -312.3436) normal (0, 0, -1) x axis (-1, 0, 0)
  line L1 (-300, -596.2019) -> (-300, 389.2686)
  line L2 (-288, -596.2019) -> (-300, -596.2019)
  line L3 (-288, 389.2686) -> (-288, -596.2019)
  line L4 (-300, 389.2686) -> (-288, 389.2686)
  line L5 (300, 389.2686) -> (300, -596.2019)
  line L6 (288, 389.2686) -> (300, 389.2686)
  line L7 (288, -596.2019) -> (288, 389.2686)
  line L8 (300, -596.2019) -> (288, -596.2019)
  line L9 (300, 389.2686) -> (-300, 389.2686)
  line L10 (300, -596.2019) -> (300, 389.2686)
  line L11 (-300, -596.2019) -> (300, -596.2019)
  line L12 (-300, 389.2686) -> (-300, -596.2019)
  line L13 (300, -103.4667) -> (-300, -103.4667)
  line L14 (300, -143.4667) -> (-300, -143.4667)
  line L15 (300, -128.4667) -> (-300, -128.4667)
  line L16 (300, -78.4667) -> (-300, -78.4667)
  line L17 (300, -63.4667) -> (-300, -63.4667)
  line L18 (300, -313.4667) -> (-300, -313.4667)
  line L19 (300, -328.4667) -> (-300, -328.4667)
  line L20 (300, -378.4667) -> (-300, -378.4667)
  line L21 (300, -393.4667) -> (-300, -393.4667)
  line L22 (300, 186.5333) -> (-300, 186.5333)
  line L23 (300, 171.5333) -> (-300, 171.5333)
  line L24 (300, 121.5333) -> (-300, 121.5333)
  line L25 (300, 106.5333) -> (-300, 106.5333)
  line L26 (-294, 389.2686) -> (-294, -596.2019)
  line L27 (294, -596.2019) -> (294, 389.2686)
  point P6 (300, -596.2019)
  point P12 (300, -596.2019)
  point P2 (-300, 389.2686)
  point P10 (-300, 389.2686)
  point P14 (-300, -103.4667)
  point P15 (300, -103.4667)
  horizontal L9
  vertical L10
  horizontal L11
  vertical L12
  coincident P6 P12
  coincident P2 P10
  midpoint L12 P14
  midpoint L5 P15
  dimension "d107" = 40
  dimension "d108" = 25
  dimension "d109" = -25
  dimension "d110" = -40
  dimension "d115" = -6
  dimension "d116" = -6
  dimension "d113" R-Pattern1-uDistance = 0
  dimension "d114" R-Pattern1-vDistance = 250
extrude "Extrude18" new body sketch "Sketch15" against normal blind 12
combine "Combine5"
combine "Combine6"
combine "Combine7"
extrude "Extrude19" cut sketch "Sketch13" profile of L1 L3 L6 L7 L8 L9 L11 L12 L13 L14 L15 L16 L17 L18 L19 L20 L21 L22 L23 L24 L25 L26 L27 L29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 against normal blind 12
combine "Combine8"
combine "Combine9"
component_from_bodies "Body->Comp1"
component_from_bodies "Body->Comp2"
component_from_bodies "Body->Comp3"
component_from_bodies "Body->Comp4"
component_from_bodies "Body->Comp5"
component_from_bodies "Body->Comp6"
component_from_bodies "Body->Comp7"
component_from_bodies "Body->Comp8"
component_from_bodies "Body->Comp9"
component_from_bodies "Body->Comp10"
combine "Combine1"
combine "Combine1"
combine "Combine1"
combine "Combine2"
combine "Combine3"
component_insert "Component Insert1"
copy_paste "CopyPaste1"
sketch "Sketch16" plane through (0, -337.8868, -90.9298) normal (0, 0.9656, 0.2599) x axis (1, 0, 0)
  line L1 (288, -233.7285) -> (300, -233.7285)
  line L2 (288, -143.475) -> (288, -233.7285)
  line L3 (-288, -143.475) -> (288, -143.475)
  line L4 (-288, -233.7285) -> (-288, -143.475)
  line L5 (-300, -233.7285) -> (-288, -233.7285)
  line L6 (-300, -293.7285) -> (-300, -233.7285)
  line L7 (-288, -293.7285) -> (-300, -293.7285)
  line L8 (-288, -383.9821) -> (-288, -293.7285)
  line L9 (288, -383.9821) -> (-288, -383.9821)
  line L10 (288, -293.7285) -> (288, -383.9821)
  line L11 (300, -293.7285) -> (288, -293.7285)
  line L12 (300, -233.7285) -> (300, -293.7285)
  line L13 (288, -143.475) -> (-288, -143.475)
  line L14 (288, -383.9821) -> (288, -143.475)
  line L15 (-288, -383.9821) -> (288, -383.9821)
  line L16 (-288, -143.475) -> (-288, -383.9821)
  line L17 (288, -263.7285) -> (-288, -263.7285)
  line L18 (0, -383.9821) -> (0, -143.475)
  line L19 (193, -383.9821) -> (193, -143.475)
  line L20 (-193, -143.475) -> (-193, -383.9821)
  point P11 (288, -383.9821)
  point P16 (288, -383.9821)
  point P5 (-288, -143.475)
  point P14 (-288, -143.475)
  point P18 (-288, -263.7285)
  point P19 (288, -263.7285)
  point P20 (0, -143.475)
  point P21 (0, -383.9821)
  horizontal L13
  vertical L14
  horizontal L15
  vertical L16
  coincident P11 P16
  coincident P5 P14
  midpoint L16 P18
  midpoint L14 P19
  midpoint L13 P20
  midpoint L9 P21
  dimension "d121" = 95
  dimension "d122" = 95
component_insert "Component Insert2"
component_insert "Component Insert3"
joint "Assemble1" OffsetX 0 OffsetY 0 OffsetZ 0 AngleZ 0 alignAngle 0 alignOffsetX 0 alignOffsetY 0 alignOffsetZ 0
joint "Assemble2" OffsetX 0 OffsetY 0 OffsetZ 0 AngleZ 0 alignAngle 0 alignOffsetX 0 alignOffsetY 0 alignOffsetZ 0
position "Position1"
combine "Combine1"
sketch "Sketch17" plane through (792.5168, -296.0368, -130.9972) normal (0, 0.9656, 0.2599) x axis (1, 0, 0)
  line L1 (-504.5168, -283.2949) -> (-492.5168, -283.2949)
  line L2 (-504.5168, -193.0414) -> (-504.5168, -283.2949)
  line L3 (-1080.5168, -193.0414) -> (-504.5168, -193.0414)
  line L4 (-1080.5168, -283.2949) -> (-1080.5168, -193.0414)
  line L5 (-1092.5168, -283.2949) -> (-1080.5168, -283.2949)
  line L6 (-1092.5168, -343.2949) -> (-1092.5168, -283.2949)
  line L7 (-1080.5168, -343.2949) -> (-1092.5168, -343.2949)
  line L8 (-1080.5168, -433.5485) -> (-1080.5168, -343.2949)
  line L9 (-504.5168, -433.5485) -> (-1080.5168, -433.5485)
  line L10 (-504.5168, -343.2949) -> (-504.5168, -433.5485)
  line L11 (-492.5168, -343.2949) -> (-504.5168, -343.2949)
  line L12 (-492.5168, -283.2949) -> (-492.5168, -343.2949)
  line L13 (-583.4884, -293.3165) -> (-615.5452, -293.3165)
  line L14 (-583.4884, -333.2734) -> (-583.4884, -293.3165)
  line L15 (-615.5452, -333.2734) -> (-583.4884, -333.2734)
  line L16 (-615.5452, -293.3165) -> (-615.5452, -333.2734)
  line L17 (-969.4884, -293.3165) -> (-1001.5452, -293.3165)
  line L18 (-969.4884, -333.2734) -> (-969.4884, -293.3165)
  line L19 (-1001.5452, -333.2734) -> (-969.4884, -333.2734)
  line L20 (-1001.5452, -293.3165) -> (-1001.5452, -333.2734)
  horizontal L13
  vertical L14
  horizontal L15
  vertical L16
  horizontal L17
  vertical L18
  horizontal L19
  vertical L20
extrude "Extrude1" cut sketch "Sketch17" profile of L13 L14 L15 L16 L17 L18 L19 L20 against normal blind 12
sketch "Sketch18" plane through (0, 0, 0) normal (0, 1, 0) x axis (1, 0, 0)
  line L1 (2840, 0) -> (400, 0)
  line L2 (2840, -1220) -> (2840, 0)
  line L3 (400, -1220) -> (2840, -1220)
  line L4 (400, 0) -> (400, -1220)
  point P2 (400, 0)
  point P3 (2840, 0)
  point P5 (400, -1220)
  horizontal L1
  vertical L2
  horizontal L3
  vertical L4
  dimension "d149" distance P2 P3 = 2440
  dimension "d150" distance P2 P5 = 1220
extrude "Extrude20" new body sketch "Sketch18" along normal blind 12
component_from_bodies "Body->Comp11"
ground "Ground1"
joint "Assemble3" alignAngle 0 alignOffsetX -850 alignOffsetY 100 alignOffsetZ 0
joint "Assemble4" alignAngle 0 alignOffsetX -225 alignOffsetY 275 alignOffsetZ 0
joint "Assemble5" alignAngle -90 alignOffsetX -700 alignOffsetY -300 alignOffsetZ 0
joint "Assemble6" alignAngle 0 alignOffsetX -200 alignOffsetY -450 alignOffsetZ 0
combine "Combine1"
joint "Assemble7" alignAngle 0 alignOffsetX -875 alignOffsetY -510 alignOffsetZ 0
joint "Assemble8" alignAngle 0 alignOffsetX -200 alignOffsetY -200 alignOffsetZ 0
joint "Assemble9" alignAngle 180 alignOffsetX -500 alignOffsetY 375 alignOffsetZ 0
joint "Assemble10" alignAngle -90 alignOffsetX 900 alignOffsetY 100 alignOffsetZ 0
sketch "Sketch19" plane through (0, 0, 0) normal (0, 1, 0) x axis (1, 0, 0)
  line L1 (2840, -1400) -> (400, -1400)
  line L2 (2840, -2620) -> (2840, -1400)
  line L3 (400, -2620) -> (2840, -2620)
  line L4 (400, -1400) -> (400, -2620)
  point P2 (400, -1400)
  point P3 (2840, -1400)
  point P5 (400, -2620)
  horizontal L1
  vertical L2
  horizontal L3
  vertical L4
  dimension "d257" distance P2 P3 = 2440
  dimension "d258" distance P2 P5 = 1220
extrude "Extrude21" new body sketch "Sketch19" along normal blind 12
joint "Assemble11" alignAngle 0 alignOffsetX -900 alignOffsetY 0 alignOffsetZ 0
joint "Assemble12" alignAngle -180 alignOffsetX -100 alignOffsetY 0 alignOffsetZ 0
joint "Assemble13" alignAngle 90 alignOffsetX -650 alignOffsetY 100 alignOffsetZ 0
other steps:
base_feature "Base Feature1"
base_feature "Base Feature1"
base_feature "Base Feature1"
base_feature "Base Feature1"
base_feature "Base Feature1"
base_feature "Base Feature1"
base_feature "Base Feature1"
base_feature "Base Feature1"
base_feature "Base Feature1"
base_feature "Base Feature1"
base_feature "Base Feature1"
create_component "CreateComponent1"
remove_body "RemoveBody1"
create_component "CreateComponent2"
remove_body "RemoveBody2"
create_component "CreateComponent3"
remove_body "RemoveBody3"
create_component "CreateComponent4"
remove_body "RemoveBody4"
create_component "CreateComponent5"
remove_body "RemoveBody5"
create_component "CreateComponent6"
remove_body "RemoveBody6"
create_component "CreateComponent7"
remove_body "RemoveBody7"
create_component "CreateComponent8"
remove_body "RemoveBody8"
create_component "CreateComponent9"
remove_body "RemoveBody9"
create_component "CreateComponent10"
remove_body "RemoveBody10"
joint_origin "JointOrigin1" sketch "Sketch16" OffsetX 0 OffsetY 0 OffsetZ 0 AngleZ 0
joint_origin "JointOrigin2" sketch "Sketch16" OffsetX 0 OffsetY 0 OffsetZ 0 AngleZ 0
create_component "CreateComponent11"
remove_body "RemoveBody11"
joint_origin "JointOrigin1" OffsetX 0 OffsetY 0 OffsetZ 0 AngleZ 0
joint_origin "JointOrigin1" OffsetX 0 OffsetY 0 OffsetZ 0 AngleZ 0
joint_origin "JointOrigin1" OffsetX 0 OffsetY 0 OffsetZ 0 AngleZ 0
joint_origin "JointOrigin2" OffsetX 0 OffsetY 0 OffsetZ 0 AngleZ 0
joint_origin "JointOrigin1" OffsetX 0 OffsetY 0 OffsetZ 0 AngleZ 0
joint_origin "JointOrigin2" OffsetX 0 OffsetY 0 OffsetZ 0 AngleZ 0
joint_origin "JointOrigin1" OffsetX 0 OffsetY 0 OffsetZ 0 AngleZ 0
joint_origin "JointOrigin3" OffsetX 0 OffsetY 0 OffsetZ 0 AngleZ 0
joint_origin "JointOrigin1" OffsetX 0 OffsetY 0 OffsetZ 0 AngleZ 0
joint_origin "JointOrigin4" OffsetX 0 OffsetY 0 OffsetZ 0 AngleZ 0
joint_origin "JointOrigin1" OffsetX 0 OffsetY 0 OffsetZ 0 AngleZ 0
joint_origin "JointOrigin5" OffsetX 0 OffsetY 0 OffsetZ 0 AngleZ 0
joint_origin "JointOrigin1" OffsetX 0 OffsetY 0 OffsetZ 0 AngleZ 0
joint_origin "JointOrigin3" OffsetX 0 OffsetY 0 OffsetZ 0 AngleZ 0
joint_origin "JointOrigin2" OffsetX 0 OffsetY 0 OffsetZ 0 AngleZ 0
joint_origin "JointOrigin6" OffsetX 0 OffsetY 0 OffsetZ 0 AngleZ 0
joint_origin "JointOrigin1" OffsetX 0 OffsetY 0 OffsetZ 0 AngleZ 0
joint_origin "JointOrigin3" OffsetX 0 OffsetY 0 OffsetZ 0 AngleZ 0
joint_origin "JointOrigin1" OffsetX 0 OffsetY 0 OffsetZ 0 AngleZ 0
joint_origin "JointOrigin4" OffsetX 0 OffsetY 0 OffsetZ 0 AngleZ 0
joint_origin "JointOrigin1" OffsetX 0 OffsetY 0 OffsetZ 0 AngleZ 0
joint_origin "JointOrigin5" OffsetX 0 OffsetY 0 OffsetZ 0 AngleZ 0

design "M5 x 0.8mm Thread 20mm LONG SOCKET HEAD CAP SCREW"
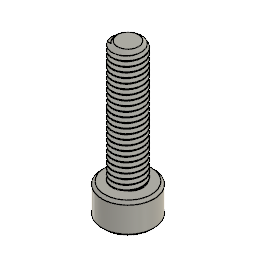
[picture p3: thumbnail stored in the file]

design "Joystick assembly"
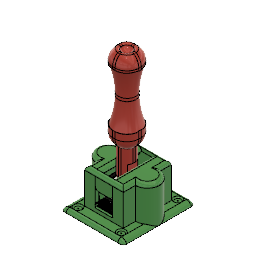
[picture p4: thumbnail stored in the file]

design "Untitled" references "M5 x 0.8mm Thread 20mm LONG SOCKET HEAD CAP SCREW", "Micro Switch de Alavanca", "Pulley 1", "42BYGH0425"
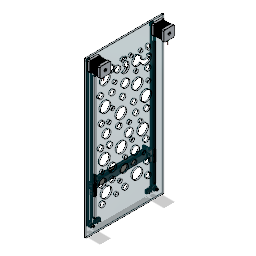
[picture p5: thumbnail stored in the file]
sketch "Sketch1" plane through (0, 0, 0) normal (1, 0, 0) x axis (0, 0, -1)
  line L1 (287, 15) -> (-13, 15)
  line L2 (287, -585) -> (287, 15)
  line L3 (-13, -585) -> (287, -585)
  line L4 (-13, 15) -> (-13, -585)
  line L5 (137, -585) -> (137, 15)
  point P6 (137, 15)
  point P7 (137, -585)
  point P2 (-13, 15)
  point P3 (287, 15)
  point P5 (-13, -585)
  horizontal L1
  vertical L2
  horizontal L3
  vertical L4
  midpoint L1 P6
  midpoint L3 P7
  dimension "d1" distance P2 P3 = 300
  dimension "d2" distance P2 P5 P3 = 600
extrude "Extrude1" new body sketch "Derived Base Feature" profile of L1 L2 L3 L4 along normal blind 6
component_insert "Component Insert1"
sketch "Sketch2" plane through (6, 0, 0) normal (1, 0, 0) x axis (0, 0, -1)
  line L1 (287, -585) -> (-13, -585)
  line L2 (287, 15) -> (287, -585)
  line L3 (-13, 15) -> (287, 15)
  line L4 (-13, -585) -> (-13, 15)
  line L5 (42, 15) -> (-13, 15)
  line L6 (42, -40) -> (42, 15)
  line L7 (-13, -40) -> (42, -40)
  line L8 (42, -40) -> (-13, 15)
  line L9 (137, -585) -> (137, 15)
  line L10 (42, -585) -> (-13, -585)
  line L11 (42, -530) -> (42, -585)
  line L12 (-13, -585) -> (42, -530)
  circle C1 centre (14.5, -12.5) radius 11
  circle C2 centre (259.5, -12.5) radius 11
  circle C3 centre (14.5, -557.5) radius 2.5
  circle C4 centre (259.5, -557.5) radius 2.5
  point P5 (-13, 15)
  point P6 (-13, 15)
  point P10 (-13, 15)
  point P11 (14.5, -12.5)
  point P2 (-13, -585)
  point P15 (-13, -585)
  point P18 (-13, -585)
  point P19 (14.5, -557.5)
  point P7 (42, 15)
  point P8 (42, -40)
  point P9 (-13, -40)
  point P16 (42, -585)
  point P17 (42, -530)
  coincident P5 P6
  perpendicular L4 L5
  perpendicular L5 L6
  horizontal L7
  coincident P5 P10
  midpoint L8 P11
  symmetric C1 L9 C2
  coincident P2 P15
  perpendicular L4 L10
  perpendicular L10 L11
  coincident P2 P18
  midpoint L12 P19
  symmetric L9 C3 C4
  dimension "d9" distance P6 P7 = 55
  dimension "d10" distance P7 P8 = 55
  dimension "d11" distance P8 P9 = 55
  dimension "d12" diameter C1 = 22
  dimension "d16" distance P16 P17 = 55
  dimension "d17" diameter C3 = 5
extrude "Extrude2" cut sketch "Sketch2" profile of C1 against normal blind 1.76
position "Position1"
combine "Combine1"
component_insert "Component Insert2"
position "Position2"
combine "Combine2"
base_feature "Base Feature1"
component_insert "Component Insert4"
position "Position3"
extrude "Extrude3" cut sketch "Sketch2" profile of C3 against normal blind 6
extrude "Extrude4" cut sketch "Sketch2" profile of C4 against normal blind 6
component_insert "Component Insert5"
component_insert "Component Insert6"
component_insert "Component Insert7"
component_insert "Component Insert8"
position "Position4"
